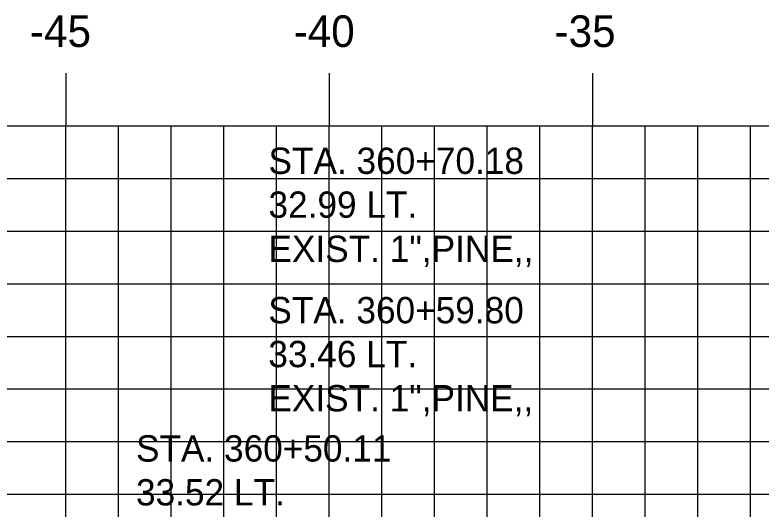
# Model space of a CAD drawing. Extents: x 1146525 to 1146695, y 608981 to 609091.
# Drawn here: x 1146561.7 to 1146575.87, y 609003.05 to 609012.44 of the extents above; entities that cross this region are included whole.
import ezdxf

# ---------------------------------------------------------------- set-up
doc = ezdxf.new("R2010")
doc.units = 0
for name, color, linetype in [('D_Text_Monospaced', 7, 'Continuous'), ('H_V ANNOTATION', 7, 'Continuous'), ('MAJOR', 7, 'Continuous'), ('MINOR', 7, 'Continuous')]:
    doc.layers.add(name, color=color, linetype=linetype)

msp = doc.modelspace()

# ---------------------------------------------------------------- linework, layer by layer
at = {"layer": 'MAJOR'}
for p, q in [((1146562.671, 609011.337), (1146562.671, 609010.335)), ((1146567.671, 609011.337), (1146567.671, 609010.335)), ((1146572.671, 609011.337), (1146572.671, 609010.335)), ((1146537.671, 609010.335), (1146677.671, 609010.335)), ((1146537.671, 609010.335), (1146677.671, 609010.335)), ((1146562.671, 608990.335), (1146562.671, 609010.335)), ((1146567.671, 608990.335), (1146567.671, 609010.335)), ((1146572.671, 608990.335), (1146572.671, 609010.335)), ((1146537.671, 609005.335), (1146677.671, 609005.335))]:
    msp.add_line(p, q, dxfattribs=at)
at = {"layer": 'MINOR'}
for p, q in [((1146563.671, 608990.335), (1146563.671, 609010.335)), ((1146564.671, 608990.335), (1146564.671, 609010.335)), ((1146565.671, 608990.335), (1146565.671, 609010.335)), ((1146566.671, 608990.335), (1146566.671, 609010.335)), ((1146568.671, 608990.335), (1146568.671, 609010.335)), ((1146569.671, 608990.335), (1146569.671, 609010.335)), ((1146570.671, 608990.335), (1146570.671, 609010.335)), ((1146571.671, 608990.335), (1146571.671, 609010.335)), ((1146573.671, 608990.335), (1146573.671, 609010.335)), ((1146574.671, 608990.335), (1146574.671, 609010.335)), ((1146575.671, 608990.335), (1146575.671, 609010.335)), ((1146537.671, 609009.335), (1146677.671, 609009.335)), ((1146537.671, 609008.335), (1146677.671, 609008.335)), ((1146537.671, 609007.335), (1146677.671, 609007.335)), ((1146537.671, 609006.335), (1146677.671, 609006.335)), ((1146537.671, 609004.335), (1146677.671, 609004.335)), ((1146537.671, 609003.335), (1146677.671, 609003.335))]:
    msp.add_line(p, q, dxfattribs=at)

# ---------------------------------------------------------------- texts
at = {"layer": 'D_Text_Monospaced'}
for s, height, p in [('STA. 360+70.18', 0.49998, (1146566.519, 609009.422)), ('32.99 LT.', 0.5, (1146566.519, 609008.588)), ('EXIST. 1",PINE,,', 0.49998, (1146566.519, 609007.748)), ('STA. 360+59.80', 0.49998, (1146566.516, 609006.583)), ('33.46 LT.', 0.5, (1146566.516, 609005.749)), ('EXIST. 1",PINE,,', 0.49998, (1146566.516, 609004.909)), ('STA. 360+50.11', 0.49998, (1146564.003, 609003.955)), ('33.52 LT.', 0.5, (1146564.003, 609003.121))]:
    msp.add_text(s, height=height, dxfattribs=at).set_placement(p)
at = {"layer": 'H_V ANNOTATION'}
for s, p in [('-45', (1146561.989, 609011.835)), ('-40', (1146566.997, 609011.835)), ('-35', (1146571.951, 609011.835))]:
    msp.add_text(s, height=0.6, dxfattribs=at).set_placement(p)

doc.saveas('drawing.dxf')
